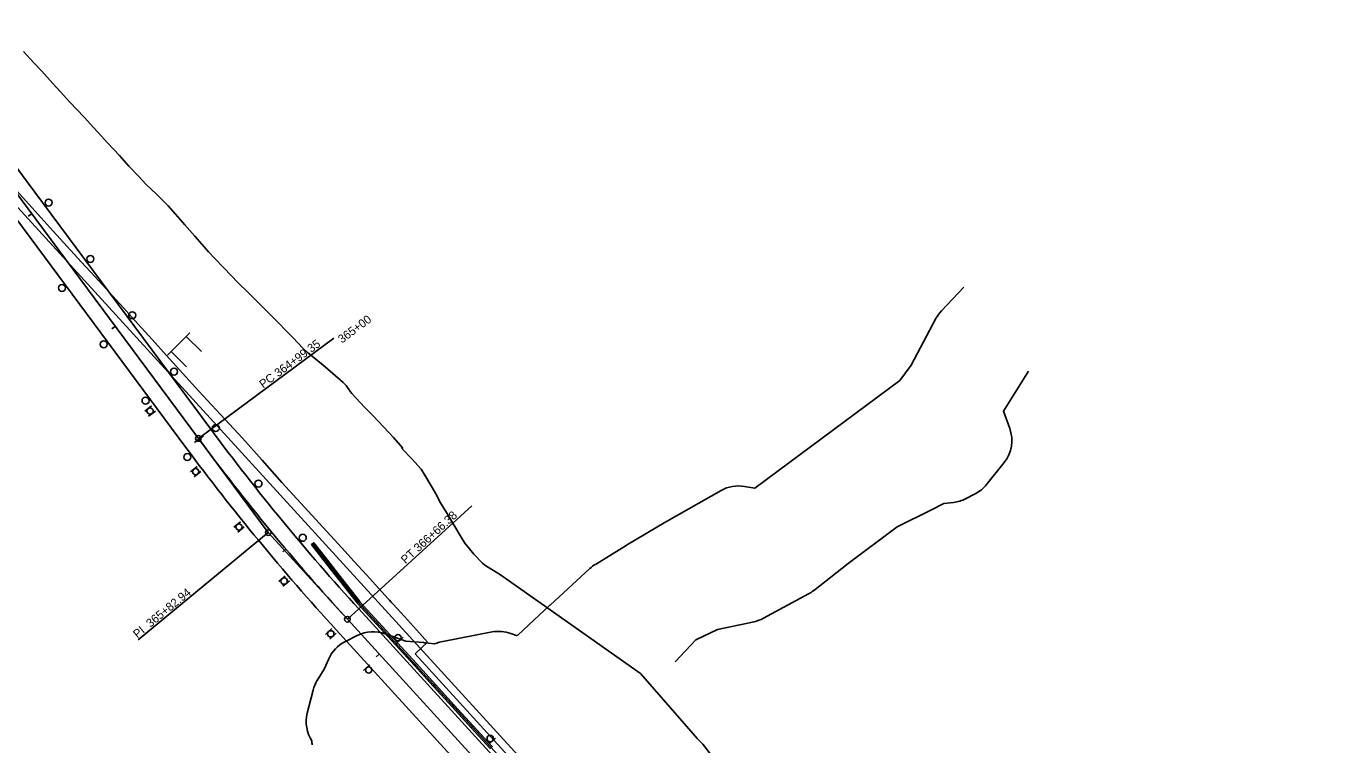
# Model space of a CAD drawing. Extents: x 1193019 to 1196816, y 1474412 to 1477212.
# Drawn here: x 1195206 to 1196137, y 1476016 to 1476528 of the extents above; entities that cross this region are included whole.
import ezdxf

# ---------------------------------------------------------------- set-up
doc = ezdxf.new("R2010")
doc.units = 0
for name, color, linetype in [('R_Draft', 7, 'Continuous'), ('R_Horz Alg', 7, 'Continuous'), ('R_Horz Alg Annot', 7, 'Continuous'), ('R_MOT', 7, 'Continuous'), ('R_No Plot', 7, 'Continuous'), ('R_Striping', 7, 'Continuous'), ('R_Water', 7, 'Continuous')]:
    doc.layers.add(name, color=color, linetype=linetype)

msp = doc.modelspace()

# ---------------------------------------------------------------- linework, layer by layer
at = {"layer": 'R_Draft'}
for p, q in [((1195482.86, 1476081.15), (1195491.79, 1476089.38)), ((1195584.25, 1475970.14), (1195482.86, 1476081.15))]:
    msp.add_line(p, q, dxfattribs=at)
for points in [[(1195203.84, 1476510.33), (1195211.19, 1476502.36), (1195216.85, 1476496.37), (1195224.76, 1476487.66), (1195230.24, 1476481.71), (1195236.95, 1476474.3), (1195247.02, 1476463.57), (1195253.66, 1476456.09), (1195257.02, 1476452.71), (1195263.71, 1476445.27), (1195272.38, 1476436.36), (1195278.83, 1476428.71), (1195285.74, 1476421.47), (1195291.34, 1476415.6), (1195298.68, 1476408.76), (1195307.05, 1476400.31), (1195312.14, 1476394.41), (1195318.75, 1476386.9), (1195325.88, 1476378.72), (1195332.56, 1476371.28), (1195335.77, 1476367.66), (1195340.27, 1476362.94), (1195346.22, 1476356.56), (1195352.35, 1476350.17), (1195356.09, 1476346.27), (1195364.71, 1476337.86), (1195369.69, 1476332.88), (1195376.62, 1476325.92), (1195383.72, 1476318.85), (1195386.58, 1476315.95), (1195390.02, 1476312.32), (1195395.79, 1476306.55), (1195396.08, 1476306.24), (1195402.96, 1476298.97), (1195406.12, 1476295.97), (1195410.95, 1476292.06), (1195418.73, 1476285.62), (1195431.6, 1476274.55), (1195433.79, 1476272.28)], [(1195491.79, 1476089.38), (1195485.93, 1476095.87), (1195475.21, 1476107.65), (1195464.5, 1476119.43), (1195465.87, 1476118.04), (1195457.06, 1476127.7), (1195448.25, 1476137.36), (1195439.44, 1476147.02), (1195430.63, 1476156.67), (1195419.96, 1476168.33), (1195409.29, 1476179.99), (1195398.62, 1476191.65), (1195387.95, 1476203.3), (1195373.9, 1476219.06), (1195359.86, 1476234.81), (1195344.29, 1476251.62), (1195328.71, 1476268.43), (1195317.19, 1476281.11), (1195305.66, 1476293.78), (1195295.47, 1476305.05), (1195285.28, 1476316.32), (1195275.09, 1476327.59), (1195264.9, 1476338.85), (1195254.95, 1476349.69), (1195245.01, 1476360.53), (1195235.06, 1476371.37), (1195225.11, 1476382.21), (1195216.37, 1476391.87), (1195207.63, 1476401.54), (1195198.89, 1476411.2)], [(1195433.79, 1476272.28), (1195436.93, 1476267.83), (1195437.67, 1476266.55), (1195446.74, 1476257.03), (1195452.43, 1476251.27), (1195460.63, 1476242.63), (1195467.38, 1476235.25), (1195473.94, 1476227.92), (1195473.55, 1476227.34), (1195480.4, 1476220.05), (1195487.22, 1476212.74), (1195489.89, 1476208.41), (1195495.12, 1476199.64), (1195497.68, 1476195.2), (1195500.89, 1476188.86), (1195505.29, 1476181.84), (1195510.49, 1476173.05), (1195515.69, 1476164.25), (1195518.38, 1476159.94)], [(1195518.38, 1476159.94), (1195521.51, 1476156.03), (1195524.64, 1476152.11), (1195530.97, 1476145.7), (1195532.54, 1476144.43), (1195543.57, 1476137.34), (1195643.34, 1476067.09), (1195674.42, 1476031.59)], [(1195674.42, 1476031.59), (1195681, 1476024.06), (1195683.84, 1476020.81), (1195687.76, 1476016.69), (1195693.88, 1476008.74)]]:
    msp.add_lwpolyline(points, dxfattribs=at)
at = {"layer": 'R_Horz Alg'}
for p, q in [((1195136.65, 1476468.36), (1196620.96, 1474843.25)), ((1195196.94, 1476411.99), (1195328.46, 1476234.64)), ((1195434.62, 1476105.79), (1195605.25, 1475918.98))]:
    msp.add_line(p, q, dxfattribs=at)
msp.add_arc((1196643.35, 1477209.79), 1637.02, 216.56127, 222.40729, dxfattribs=at)
at = {"layer": 'R_Horz Alg Annot'}
for p, q in [((1195328.46, 1476234.64), (1195378.25, 1476167.51)), ((1195378.25, 1476167.51), (1195434.62, 1476105.79))]:
    msp.add_line(p, q, dxfattribs=at)
for points in [[(1195207.3, 1476392.98), (1195209.71, 1476394.77)], [(1195266.87, 1476312.66), (1195269.28, 1476314.45)], [(1195328.46, 1476234.64), (1195424.85, 1476306.13)], [(1195332.06, 1476236.51), (1195325.64, 1476231.74)], [(1195434.62, 1476105.79), (1195523.23, 1476186.71)], [(1195378.25, 1476167.51), (1195285.64, 1476091.2)], [(1195388.57, 1476153.76), (1195390.86, 1476155.7)], [(1195455.08, 1476078.94), (1195457.3, 1476080.96)]]:
    msp.add_lwpolyline(points, dxfattribs=at)
for centre in [(1195328.46, 1476234.64), (1195378.25, 1476167.51), (1195434.62, 1476105.79)]:
    msp.add_circle(centre, 2, dxfattribs=at)
at = {"layer": 'R_MOT'}
for p, q in [((1195306.44, 1476293.89), (1195322.3, 1476309.86)), ((1195330.71, 1476296.54), (1195319.81, 1476307.36)), ((1195319.95, 1476285.7), (1195309.06, 1476296.52)), ((1195290.32, 1476254.14), (1195295.09, 1476257.77)), ((1195297.82, 1476254.19), (1195293.04, 1476250.56)), ((1195322.79, 1476210.94), (1195327.56, 1476214.57)), ((1195330.29, 1476210.99), (1195325.51, 1476207.36)), ((1195353.7, 1476171.34), (1195358.36, 1476175.12)), ((1195361.19, 1476171.62), (1195356.53, 1476167.84)), ((1195385.79, 1476132.7), (1195390.34, 1476136.61)), ((1195393.27, 1476133.2), (1195388.73, 1476129.29)), ((1195419.04, 1476095.05), (1195423.47, 1476099.1)), ((1195426.51, 1476095.78), (1195422.08, 1476091.73)), ((1195474.37, 1476092.96), (1195469.94, 1476088.91)), ((1195446.07, 1476069.3), (1195450.49, 1476073.35)), ((1195540.07, 1476021.17), (1195535.65, 1476017.12))]:
    msp.add_line(p, q, dxfattribs=at)
for points in [[(1195417.18, 1476148.71), (1195409.11, 1476159.03), (1195410.69, 1476160.26), (1195418.75, 1476149.94)], [(1195429.5, 1476132.95), (1195417.18, 1476148.71), (1195418.75, 1476149.94), (1195431.07, 1476134.19)], [(1195441.81, 1476117.2), (1195429.5, 1476132.95), (1195431.07, 1476134.19), (1195443.39, 1476118.43)], [(1195443.34, 1476118.49), (1195456.83, 1476103.72), (1195455.35, 1476102.37), (1195441.86, 1476117.14)], [(1195456.83, 1476103.72), (1195470.31, 1476088.95), (1195468.84, 1476087.6), (1195455.35, 1476102.37)], [(1195470.31, 1476088.95), (1195483.8, 1476074.19), (1195482.33, 1476072.84), (1195468.84, 1476087.6)], [(1195483.8, 1476074.19), (1195497.29, 1476059.42), (1195495.81, 1476058.07), (1195482.33, 1476072.84)], [(1195497.29, 1476059.42), (1195510.78, 1476044.65), (1195509.3, 1476043.3), (1195495.81, 1476058.07)], [(1195510.78, 1476044.65), (1195524.27, 1476029.88), (1195522.79, 1476028.53), (1195509.3, 1476043.3)], [(1195524.27, 1476029.88), (1195537.75, 1476015.12), (1195536.28, 1476013.77), (1195522.79, 1476028.53)]]:
    msp.add_lwpolyline(points, close=True, dxfattribs=at)
for points in [[(1195442.6, 1476117.81), (1195409.95, 1476159.59)], [(1195617.94, 1475925.84), (1195442.6, 1476117.81)], [(1195617.94, 1475925.84), (1195442.6, 1476117.81)]]:
    msp.add_lwpolyline(points, dxfattribs=at)
for centre, radius in [((1195221.75, 1476402.7), 2.5), ((1195251.53, 1476362.54), 2.5), ((1195231.25, 1476341.86), 2.5), ((1195281.32, 1476322.38), 2.5), ((1195261.03, 1476301.7), 2.5), ((1195311.1, 1476282.22), 2.5), ((1195311.1, 1476282.22), 2.5), ((1195290.81, 1476261.54), 2.5), ((1195294.07, 1476254.17), 2.25), ((1195294.07, 1476254.17), 2.25), ((1195340.89, 1476242.06), 2.5), ((1195320.6, 1476221.38), 2.5), ((1195326.54, 1476210.97), 2.25), ((1195326.54, 1476210.97), 2.25), ((1195371.25, 1476202.47), 2.5), ((1195357.44, 1476171.48), 2.25), ((1195357.44, 1476171.48), 2.25), ((1195402.83, 1476163.84), 2.5), ((1195389.53, 1476132.95), 2.25), ((1195389.53, 1476132.95), 2.25), ((1195422.77, 1476095.41), 2.25), ((1195422.77, 1476095.41), 2.25), ((1195470.64, 1476092.59), 2.25), ((1195449.8, 1476069.67), 2.25), ((1195536.34, 1476020.8), 2.25)]:
    msp.add_circle(centre, radius, dxfattribs=at)
at = {"layer": 'R_No Plot'}
for p, q in [((1195444.96, 1476115.23), (1195615.58, 1475928.42)), ((1195482.87, 1476081.15), (1195491.79, 1476089.38)), ((1195482.87, 1476081.15), (1195491.79, 1476089.38)), ((1195584.26, 1475970.14), (1195482.87, 1476081.15)), ((1195584.26, 1475970.14), (1195482.87, 1476081.15))]:
    msp.add_line(p, q, dxfattribs=at)
for points in [[(1195491.79, 1476089.38), (1195485.93, 1476095.87), (1195475.21, 1476107.65), (1195464.5, 1476119.43), (1195465.87, 1476118.04), (1195457.06, 1476127.7), (1195448.25, 1476137.36), (1195439.44, 1476147.02), (1195430.63, 1476156.67), (1195419.96, 1476168.33), (1195409.29, 1476179.99), (1195398.62, 1476191.65), (1195387.95, 1476203.3), (1195373.9, 1476219.06), (1195359.86, 1476234.81), (1195344.29, 1476251.62), (1195328.71, 1476268.43), (1195317.19, 1476281.11), (1195305.66, 1476293.78), (1195295.47, 1476305.05), (1195285.28, 1476316.32), (1195275.09, 1476327.59), (1195264.9, 1476338.85), (1195254.95, 1476349.69), (1195245.01, 1476360.53), (1195235.06, 1476371.37), (1195225.11, 1476382.21), (1195216.37, 1476391.87), (1195207.63, 1476401.54), (1195198.89, 1476411.2)], [(1195491.79, 1476089.38), (1195485.93, 1476095.87), (1195475.21, 1476107.65), (1195464.5, 1476119.43), (1195465.87, 1476118.04), (1195457.06, 1476127.7), (1195448.25, 1476137.36), (1195439.44, 1476147.02), (1195430.63, 1476156.67), (1195419.96, 1476168.33), (1195409.29, 1476179.99), (1195398.62, 1476191.65), (1195387.95, 1476203.3), (1195373.9, 1476219.06), (1195359.86, 1476234.81), (1195344.29, 1476251.62), (1195328.71, 1476268.43), (1195317.19, 1476281.11), (1195305.66, 1476293.78), (1195295.47, 1476305.05), (1195285.28, 1476316.32), (1195275.09, 1476327.59), (1195264.9, 1476338.85), (1195254.95, 1476349.69), (1195245.01, 1476360.53), (1195235.06, 1476371.37), (1195225.11, 1476382.21), (1195216.37, 1476391.87), (1195207.63, 1476401.54), (1195198.89, 1476411.2)], [(1195442.6, 1476117.81), (1195409.95, 1476159.59)]]:
    msp.add_lwpolyline(points, dxfattribs=at)
at = {"layer": 'R_Striping'}
for p, q in [((1195205.78, 1476418.54), (1195337.3, 1476241.2)), ((1195196.94, 1476411.99), (1195328.46, 1476234.64)), ((1195188.11, 1476405.43), (1195319.63, 1476228.09)), ((1195442.75, 1476113.21), (1195613.37, 1475926.4)), ((1195434.62, 1476105.79), (1195605.25, 1475918.98)), ((1195426.5, 1476098.37), (1195597.12, 1475911.56))]:
    msp.add_line(p, q, dxfattribs=at)
for centre, radius, start, end in [((1193882.05, 1475436.84), 1648.02, 36.56127, 46.31104), ((1196643.35, 1477209.79), 1626.02, 216.56127, 222.40729), ((1196643.35, 1477209.79), 1637.02, 216.56127, 222.40729), ((1196643.35, 1477209.79), 1648.02, 216.56127, 222.40729)]:
    msp.add_arc(centre, radius, start, end, dxfattribs=at)
at = {"layer": 'R_Water'}
for p, q in [((1195857.73, 1476325.49), (1195873.65, 1476342.37)), ((1195889.93, 1476201.84), (1195902.45, 1476217.51)), ((1195661.93, 1476175.42), (1195700.84, 1476197.54)), ((1195875.01, 1476191.67), (1195881.92, 1476195.26)), ((1195633.44, 1476158.52), (1195661.54, 1476175.19)), ((1195611.24, 1476144.9), (1195633.12, 1476158.33)), ((1195578.97, 1476115.86), (1195607.39, 1476141.99)), ((1195730.96, 1476106.52), (1195763.04, 1476123.84)), ((1195432.81, 1476089.74), (1195441.64, 1476094.24)), ((1195502.5, 1476089.99), (1195537.69, 1476096.73)), ((1195406.04, 1476038.81), (1195410.18, 1476055.26))]:
    msp.add_line(p, q, dxfattribs=at)
for points in [[(1195717.47, 1476200.45), (1195724.84, 1476199.17), (1195828.26, 1476276), (1195836.29, 1476286.82), (1195853.81, 1476320.01)], [(1195906.4, 1476241.68), (1195901.9, 1476254.04), (1195919.81, 1476282.49)], [(1195850.77, 1476183.81), (1195859.58, 1476188.22), (1195866.44, 1476189.04)], [(1195766.6, 1476126.17), (1195791.33, 1476145.59), (1195826.3, 1476171.68), (1195850.67, 1476183.76)], [(1195550.93, 1476095.67), (1195555.12, 1476094.15), (1195556, 1476094.44), (1195578.85, 1476115.74)], [(1195668.11, 1476075.57), (1195682.75, 1476091.12), (1195698.18, 1476098.43), (1195724.35, 1476104.08)], [(1195461.56, 1476095.46), (1195476.18, 1476090.13), (1195488.89, 1476089.18)], [(1195490.26, 1476089.04), (1195496.73, 1476088.2), (1195498.33, 1476088.81)], [(1195413.15, 1476062.28), (1195418.01, 1476070.16), (1195421.33, 1476077.62)]]:
    msp.add_lwpolyline(points, dxfattribs=at)
for centre, start, end in [((1195875.92, 1476308.34), 136.68505, 152.17076), ((1195882.92, 1476233.11), 321.37089, 20.03003), ((1195713.2, 1476175.81), 80.15542, 119.63021), ((1195870.4, 1476217.45), 297.43431, 321.37089), ((1195863.49, 1476213.86), 276.7699, 297.43431), ((1195839.57, 1476206.16), 296.35633, 296.61547), ((1195674.29, 1476153.68), 119.63021, 120.66985), ((1195646.2, 1476137.02), 120.66985, 121.53823), ((1195624.31, 1476123.59), 121.53823, 132.6037), ((1195751.16, 1476145.84), 298.36807, 308.13773), ((1195595.9, 1476097.46), 132.6037, 132.99721), ((1195719.08, 1476128.52), 282.17905, 298.36807), ((1195453, 1476071.97), 69.96238, 117.02815), ((1195542.39, 1476072.17), 70.03404, 100.83981), ((1195444.17, 1476067.47), 117.02815, 156.0394), ((1195487.03, 1476064.25), 82.58387, 85.74275), ((1195507.2, 1476065.43), 100.83981, 110.79523), ((1195434.43, 1476049.16), 148.32547, 165.87287), ((1195430.29, 1476032.71), 165.87287, 212.87014), ((1195434.26, 1476020.34), 182.73754, 189.26756)]:
    msp.add_arc(centre, 25, start, end, dxfattribs=at)

# ---------------------------------------------------------------- texts
at = {"layer": 'R_Horz Alg Annot'}
for s, rotation, p in [('365+00', 36.58391, (1195430.69, 1476302.15)), ('PC 364+99.35', 36.56127, (1195374.62, 1476270.12)), ('PT 366+66.38', 42.40729, (1195476.02, 1476144.95)), ('PI  365+82.94', 39.48428, (1195285, 1476091.97))]:
    msp.add_text(s, height=6, rotation=rotation, dxfattribs=at).set_placement(p)

doc.saveas('drawing.dxf')
